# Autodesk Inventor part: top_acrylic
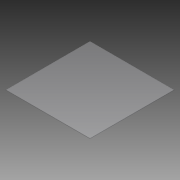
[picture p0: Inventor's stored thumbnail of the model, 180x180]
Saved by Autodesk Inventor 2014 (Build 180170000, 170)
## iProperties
Created: 2014-05
Part Number: top_acrylic
Material: Acrylic, Clear
Document SubType Name: Modeling
Designer: t_emanb
Density: 1.19 g/cm^3
Appearance: Transparent - Clear
Author: t_emanb
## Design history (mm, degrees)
sketch "Sketch1"
  geometry: L1 (0, 0)-(609.6, 0); L2 (609.6, 0)-(609.6, 609.6); L3 (609.6, 609.6)-(0, 609.6); L4 (0, 609.6)-(0, 0)
  constraints: 8 end point, 2 parallel, 1 horizontal, 1 perpendicular
  dimensions: "d0" = 609.6 distance of L1.start L1.end; "d1" = 609.6 distance of L3.end L1.start
extrude "Extrusion1" new body sketch "Sketch1" distance "d2" = 3.0988; taper "d3" = 0 deg
body "Solid1"
